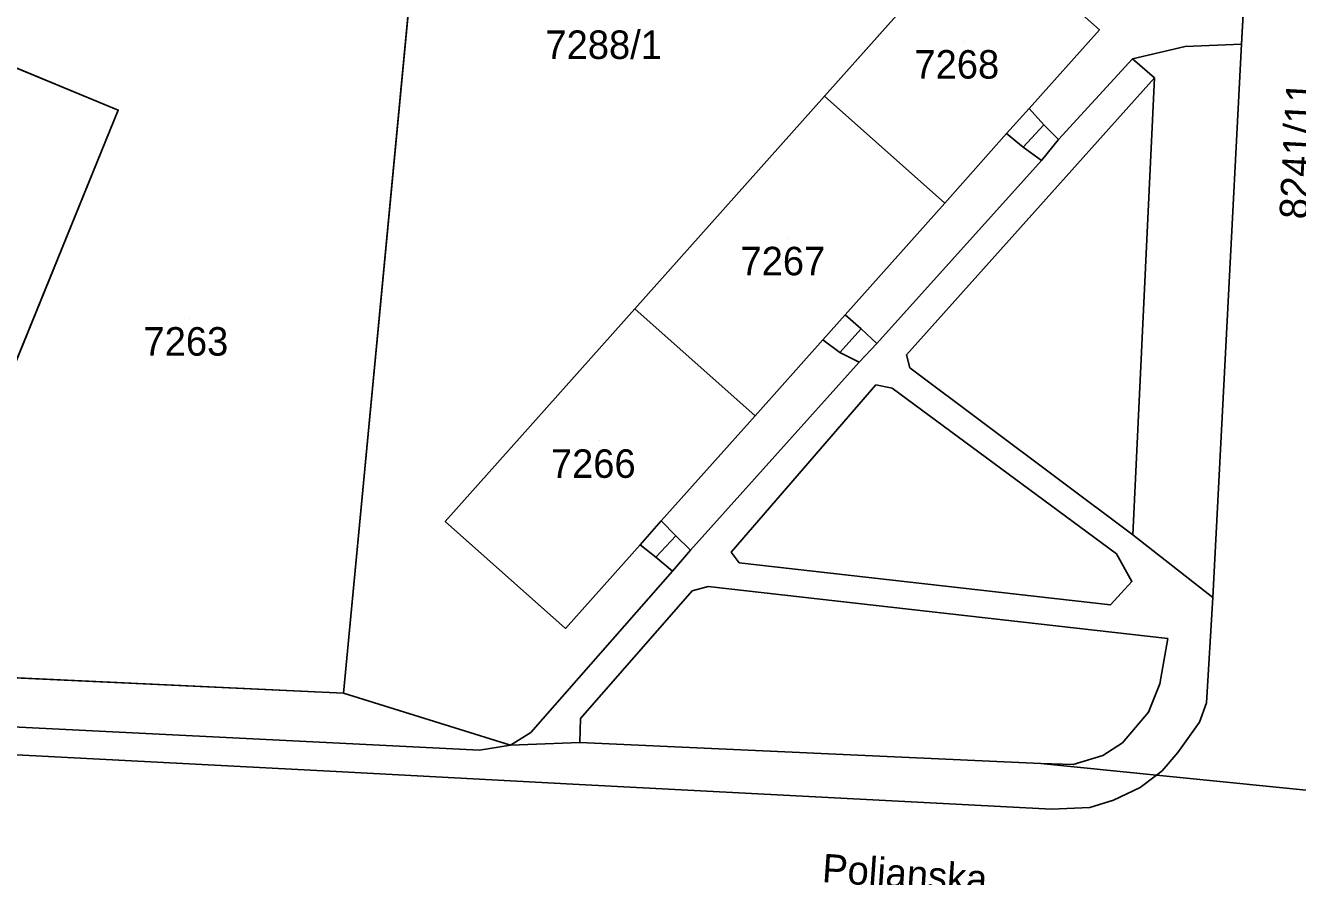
# Model space of a CAD drawing. Extents: x -266199 to -261993, y -1239047 to -1235108.
# Drawn here: x -263673.7 to -263584.5, y -1236465.2 to -1236405.4 of the extents above; entities that cross this region are included whole.
import ezdxf

# ---------------------------------------------------------------- set-up
doc = ezdxf.new("R2010")
doc.units = 0
for name, color, linetype in [('body_kn', 7, 'Continuous'), ('kladpar_druhypozemkov', 7, 'Continuous'), ('kladpar_hranice', 7, 'Continuous'), ('kladpar_parcelnecisla', 7, 'Continuous'), ('kladpar_plochy', 7, 'Continuous'), ('popisy', 7, 'Continuous'), ('zappar_hrandruhpozemk', 7, 'Continuous')]:
    doc.layers.add(name, color=color, linetype=linetype)

msp = doc.modelspace()

# ---------------------------------------------------------------- linework, layer by layer
at = {"layer": 'body_kn'}
for p, q in [((-263598.37, -1236405.73), (-263598.37, -1236405.73)), ((-263592.36, -1236406.91), (-263592.36, -1236406.91)), ((-263588.4, -1236406.75), (-263588.4, -1236406.75)), ((-263588.4, -1236406.75), (-263588.4, -1236406.75)), ((-263596.04, -1236407.78), (-263596.04, -1236407.78)), ((-263596.04, -1236407.78), (-263596.04, -1236407.78)), ((-263594.51, -1236409.11), (-263594.51, -1236409.11)), ((-263594.51, -1236409.11), (-263594.51, -1236409.11)), ((-263617.67, -1236410.39), (-263617.67, -1236410.39)), ((-263617.67, -1236410.39), (-263617.67, -1236410.39)), ((-263667.24, -1236411.37), (-263667.24, -1236411.37)), ((-263603.3, -1236411.26), (-263603.3, -1236411.26)), ((-263602.28, -1236412.4), (-263602.28, -1236412.4)), ((-263604.88, -1236413.02), (-263604.88, -1236413.02)), ((-263604.88, -1236413.02), (-263604.88, -1236413.02)), ((-263601.25, -1236413.44), (-263601.25, -1236413.44)), ((-263601.25, -1236413.44), (-263601.25, -1236413.44)), ((-263603.72, -1236413.98), (-263603.72, -1236413.98)), ((-263603.72, -1236413.98), (-263603.72, -1236413.98)), ((-263602.43, -1236414.91), (-263602.43, -1236414.91)), ((-263609.23, -1236417.91), (-263609.23, -1236417.91)), ((-263609.23, -1236417.91), (-263609.23, -1236417.91)), ((-263630.98, -1236425.33), (-263630.98, -1236425.33)), ((-263630.98, -1236425.33), (-263630.98, -1236425.33)), ((-263616.21, -1236425.74), (-263616.21, -1236425.74)), ((-263615.1, -1236426.73), (-263615.1, -1236426.73)), ((-263617.78, -1236427.5), (-263617.78, -1236427.5)), ((-263617.78, -1236427.5), (-263617.78, -1236427.5)), ((-263613.99, -1236427.76), (-263613.99, -1236427.76)), ((-263613.99, -1236427.76), (-263613.99, -1236427.76)), ((-263616.59, -1236428.4), (-263616.59, -1236428.4)), ((-263616.59, -1236428.4), (-263616.59, -1236428.4)), ((-263611.9, -1236428.55), (-263611.9, -1236428.55)), ((-263611.9, -1236428.55), (-263611.9, -1236428.55)), ((-263615.24, -1236429.07), (-263615.24, -1236429.07)), ((-263611.67, -1236429.47), (-263611.67, -1236429.47)), ((-263614.05, -1236430.67), (-263614.05, -1236430.67)), ((-263612.92, -1236430.89), (-263612.92, -1236430.89)), ((-263622.54, -1236432.83), (-263622.54, -1236432.83)), ((-263622.54, -1236432.83), (-263622.54, -1236432.83)), ((-263644.28, -1236440.26), (-263644.28, -1236440.26)), ((-263644.28, -1236440.26), (-263644.28, -1236440.26)), ((-263629.13, -1236440.22), (-263629.13, -1236440.22)), ((-263628.1, -1236441.27), (-263628.1, -1236441.27)), ((-263596.02, -1236441.19), (-263596.02, -1236441.19)), ((-263630.61, -1236441.89), (-263630.61, -1236441.89)), ((-263630.61, -1236441.89), (-263630.61, -1236441.89)), ((-263627.07, -1236442.26), (-263627.07, -1236442.26)), ((-263627.07, -1236442.26), (-263627.07, -1236442.26)), ((-263629.51, -1236442.76), (-263629.51, -1236442.76)), ((-263629.51, -1236442.76), (-263629.51, -1236442.76)), ((-263624.21, -1236442.4), (-263624.21, -1236442.4)), ((-263623.66, -1236443.15), (-263623.66, -1236443.15)), ((-263623.66, -1236443.15), (-263623.66, -1236443.15)), ((-263597.18, -1236442.53), (-263597.18, -1236442.53)), ((-263628.33, -1236443.75), (-263628.33, -1236443.75)), ((-263625.82, -1236444.81), (-263625.82, -1236444.81)), ((-263596.09, -1236444.47), (-263596.09, -1236444.47)), ((-263626.95, -1236445.13), (-263626.95, -1236445.13)), ((-263590.41, -1236445.58), (-263590.41, -1236445.58)), ((-263597.59, -1236446.11), (-263597.59, -1236446.11)), ((-263635.85, -1236447.76), (-263635.85, -1236447.76)), ((-263593.56, -1236448.48), (-263593.56, -1236448.48)), ((-263594.12, -1236451.65), (-263594.12, -1236451.65)), ((-263651.42, -1236452.3), (-263651.42, -1236452.3)), ((-263590.85, -1236452.98), (-263590.85, -1236452.98)), ((-263594.93, -1236453.64), (-263594.93, -1236453.64)), ((-263634.79, -1236454.08), (-263634.79, -1236454.08)), ((-263591.34, -1236454.35), (-263591.34, -1236454.35)), ((-263638.28, -1236455.08), (-263638.28, -1236455.08)), ((-263641.87, -1236456.31), (-263641.87, -1236456.31)), ((-263639.7, -1236455.97), (-263639.7, -1236455.97)), ((-263639.7, -1236455.97), (-263639.7, -1236455.97)), ((-263634.84, -1236455.76), (-263634.84, -1236455.76)), ((-263596.75, -1236455.79), (-263596.75, -1236455.79)), ((-263592.86, -1236456.48), (-263592.86, -1236456.48)), ((-263602.47, -1236457.24), (-263602.47, -1236457.24)), ((-263602.47, -1236457.24), (-263602.47, -1236457.24)), ((-263600.21, -1236457.31), (-263600.21, -1236457.31)), ((-263598.13, -1236456.69), (-263598.13, -1236456.69)), ((-263651.94, -1236457.81), (-263651.94, -1236457.81)), ((-263594.37, -1236458.06), (-263594.37, -1236458.06)), ((-263594.37, -1236458.06), (-263594.37, -1236458.06)), ((-263593.97, -1236457.75), (-263593.97, -1236457.75)), ((-263635.34, -1236458.69), (-263635.34, -1236458.69)), ((-263595.51, -1236458.93), (-263595.51, -1236458.93)), ((-263597.38, -1236459.82), (-263597.38, -1236459.82)), ((-263601.74, -1236460.46), (-263601.74, -1236460.46)), ((-263599.04, -1236460.33), (-263599.04, -1236460.33))]:
    msp.add_line(p, q, dxfattribs=at)
at = {"layer": 'kladpar_druhypozemkov'}
for p, q in [((-263607.89, -1236406.56), (-263607.89, -1236406.56)), ((-263620.17, -1236420.37), (-263620.17, -1236420.37)), ((-263662.21, -1236426.01), (-263662.21, -1236426.01)), ((-263633.43, -1236434.59), (-263633.43, -1236434.59))]:
    msp.add_line(p, q, dxfattribs=at)
at = {"layer": 'kladpar_hranice'}
for p, q in [((-263630.98, -1236425.33), (-263617.67, -1236410.39)), ((-263609.23, -1236417.91), (-263617.67, -1236410.39)), ((-263617.67, -1236410.39), (-263609.23, -1236417.91)), ((-263644.28, -1236440.26), (-263630.98, -1236425.33)), ((-263622.54, -1236432.83), (-263630.98, -1236425.33)), ((-263630.98, -1236425.33), (-263622.54, -1236432.83))]:
    msp.add_line(p, q, dxfattribs=at)
for points in [[(-263581.51, -1236459.36), (-263594.37, -1236458.06), (-263602.47, -1236457.24), (-263634.84, -1236455.76), (-263639.7, -1236455.97), (-263638.28, -1236455.08), (-263628.33, -1236443.75), (-263627.07, -1236442.26), (-263615.24, -1236429.07), (-263613.99, -1236427.76), (-263602.43, -1236414.91), (-263601.25, -1236413.44), (-263596.04, -1236407.78), (-263592.36, -1236406.91), (-263588.4, -1236406.75), (-263587.17, -1236384.74), (-263588.09, -1236383.59), (-263587.23, -1236367.19), (-263586.62, -1236353.93), (-263586.06, -1236340.81)], [(-263639.7, -1236455.97), (-263651.42, -1236452.3), (-263646.39, -1236399.38), (-263633.39, -1236364.05), (-263622.98, -1236368.95), (-263588.09, -1236383.59), (-263587.17, -1236384.74), (-263588.4, -1236406.75), (-263592.36, -1236406.91), (-263596.04, -1236407.78), (-263601.25, -1236413.44), (-263602.43, -1236414.91), (-263613.99, -1236427.76), (-263615.24, -1236429.07), (-263627.07, -1236442.26), (-263628.33, -1236443.75), (-263638.28, -1236455.08), (-263639.7, -1236455.97)], [(-263709.09, -1236449.61), (-263705.05, -1236441.25), (-263700.39, -1236432.21), (-263697.06, -1236424.67), (-263693.98, -1236417.08), (-263691.05, -1236409.36), (-263688.46, -1236401.51), (-263685.97, -1236393.68), (-263684.19, -1236387.52), (-263683.79, -1236386.13), (-263681.38, -1236386.98), (-263646.39, -1236399.38), (-263651.42, -1236452.3), (-263702.72, -1236449.91), (-263705.18, -1236449.79), (-263709.09, -1236449.61)], [(-263606.83, -1236398.22), (-263617.67, -1236410.39), (-263630.98, -1236425.33), (-263644.28, -1236440.26), (-263635.85, -1236447.76), (-263630.61, -1236441.89), (-263629.51, -1236442.76), (-263628.1, -1236441.27), (-263629.13, -1236440.22), (-263622.54, -1236432.83), (-263617.78, -1236427.5), (-263616.59, -1236428.4), (-263615.1, -1236426.73), (-263616.21, -1236425.74), (-263609.23, -1236417.91), (-263604.88, -1236413.02), (-263603.72, -1236413.98), (-263602.28, -1236412.4), (-263603.3, -1236411.26), (-263598.37, -1236405.73), (-263606.83, -1236398.22)], [(-263617.67, -1236410.39), (-263606.83, -1236398.22), (-263598.37, -1236405.73), (-263603.3, -1236411.26), (-263602.28, -1236412.4), (-263603.72, -1236413.98), (-263604.88, -1236413.02), (-263609.23, -1236417.91)], [(-263680.05, -1236442.84), (-263667.24, -1236411.37), (-263675.8, -1236407.84)], [(-263675.8, -1236407.84), (-263667.24, -1236411.37), (-263680.05, -1236442.84)], [(-263609.23, -1236417.91), (-263616.21, -1236425.74), (-263615.1, -1236426.73), (-263616.59, -1236428.4), (-263617.78, -1236427.5), (-263622.54, -1236432.83)], [(-263622.54, -1236432.83), (-263629.13, -1236440.22), (-263628.1, -1236441.27), (-263629.51, -1236442.76), (-263630.61, -1236441.89), (-263635.85, -1236447.76), (-263644.28, -1236440.26)], [(-263722.34, -1236467.48), (-263719.3, -1236463.54), (-263712.51, -1236454.77), (-263710.25, -1236451.5), (-263709.09, -1236449.61), (-263705.18, -1236449.79), (-263702.72, -1236449.91), (-263651.42, -1236452.3), (-263639.7, -1236455.97), (-263634.84, -1236455.76), (-263602.47, -1236457.24), (-263594.37, -1236458.06), (-263581.51, -1236459.36), (-263579.99, -1236460.55), (-263578.24, -1236461.24), (-263575.93, -1236461.68), (-263573.66, -1236461.77), (-263543.38, -1236463.29), (-263540.94, -1236463.26), (-263529.02, -1236464.2), (-263526.42, -1236463.65), (-263524.5, -1236462.92), (-263525.44, -1236474.41)]]:
    msp.add_lwpolyline(points, dxfattribs=at)
at = {"layer": 'kladpar_plochy'}
for p, q in [((-263587.17, -1236384.74), (-263588.4, -1236406.75)), ((-263606.83, -1236398.22), (-263617.67, -1236410.39)), ((-263598.37, -1236405.73), (-263606.83, -1236398.22)), ((-263651.42, -1236452.3), (-263646.39, -1236399.38)), ((-263646.39, -1236399.38), (-263651.42, -1236452.3)), ((-263603.3, -1236411.26), (-263598.37, -1236405.73)), ((-263592.36, -1236406.91), (-263596.04, -1236407.78)), ((-263588.4, -1236406.75), (-263592.36, -1236406.91)), ((-263667.24, -1236411.37), (-263675.8, -1236407.84)), ((-263596.04, -1236407.78), (-263601.25, -1236413.44)), ((-263617.67, -1236410.39), (-263630.98, -1236425.33)), ((-263680.05, -1236442.84), (-263667.24, -1236411.37)), ((-263602.28, -1236412.4), (-263603.3, -1236411.26)), ((-263603.72, -1236413.98), (-263602.28, -1236412.4)), ((-263609.23, -1236417.91), (-263604.88, -1236413.02)), ((-263604.88, -1236413.02), (-263603.72, -1236413.98)), ((-263601.25, -1236413.44), (-263602.43, -1236414.91)), ((-263602.43, -1236414.91), (-263613.99, -1236427.76)), ((-263616.21, -1236425.74), (-263609.23, -1236417.91)), ((-263630.98, -1236425.33), (-263644.28, -1236440.26)), ((-263615.1, -1236426.73), (-263616.21, -1236425.74)), ((-263616.59, -1236428.4), (-263615.1, -1236426.73)), ((-263622.54, -1236432.83), (-263617.78, -1236427.5)), ((-263617.78, -1236427.5), (-263616.59, -1236428.4)), ((-263613.99, -1236427.76), (-263615.24, -1236429.07)), ((-263615.24, -1236429.07), (-263627.07, -1236442.26)), ((-263629.13, -1236440.22), (-263622.54, -1236432.83)), ((-263644.28, -1236440.26), (-263635.85, -1236447.76)), ((-263628.1, -1236441.27), (-263629.13, -1236440.22)), ((-263629.51, -1236442.76), (-263628.1, -1236441.27)), ((-263635.85, -1236447.76), (-263630.61, -1236441.89)), ((-263630.61, -1236441.89), (-263629.51, -1236442.76)), ((-263627.07, -1236442.26), (-263628.33, -1236443.75)), ((-263628.33, -1236443.75), (-263638.28, -1236455.08)), ((-263651.42, -1236452.3), (-263702.72, -1236449.91)), ((-263639.7, -1236455.97), (-263651.42, -1236452.3)), ((-263638.28, -1236455.08), (-263639.7, -1236455.97))]:
    msp.add_line(p, q, dxfattribs=at)
for points in [[(-263581.51, -1236459.36), (-263594.37, -1236458.06), (-263602.47, -1236457.24), (-263634.84, -1236455.76), (-263639.7, -1236455.97), (-263638.28, -1236455.08), (-263628.33, -1236443.75), (-263627.07, -1236442.26), (-263615.24, -1236429.07), (-263613.99, -1236427.76), (-263602.43, -1236414.91), (-263601.25, -1236413.44), (-263596.04, -1236407.78), (-263592.36, -1236406.91), (-263588.4, -1236406.75), (-263587.17, -1236384.74), (-263588.09, -1236383.59), (-263587.23, -1236367.19), (-263586.62, -1236353.93), (-263586.06, -1236340.81)], [(-263675.8, -1236407.84), (-263667.24, -1236411.37), (-263680.05, -1236442.84)], [(-263722.34, -1236467.48), (-263719.3, -1236463.54), (-263712.51, -1236454.77), (-263710.25, -1236451.5), (-263709.09, -1236449.61), (-263705.18, -1236449.79), (-263702.72, -1236449.91), (-263651.42, -1236452.3), (-263639.7, -1236455.97), (-263634.84, -1236455.76), (-263602.47, -1236457.24), (-263594.37, -1236458.06), (-263581.51, -1236459.36), (-263579.99, -1236460.55), (-263578.24, -1236461.24), (-263575.93, -1236461.68), (-263573.66, -1236461.77), (-263543.38, -1236463.29), (-263540.94, -1236463.26), (-263529.02, -1236464.2), (-263526.42, -1236463.65), (-263524.5, -1236462.92), (-263525.44, -1236474.41)]]:
    msp.add_lwpolyline(points, dxfattribs=at)
for points in [[(-263617.67, -1236410.39), (-263606.83, -1236398.22), (-263598.37, -1236405.73), (-263603.3, -1236411.26), (-263602.28, -1236412.4), (-263603.72, -1236413.98), (-263604.88, -1236413.02), (-263609.23, -1236417.91)], [(-263630.98, -1236425.33), (-263617.67, -1236410.39), (-263609.23, -1236417.91), (-263616.21, -1236425.74), (-263615.1, -1236426.73), (-263616.59, -1236428.4), (-263617.78, -1236427.5), (-263622.54, -1236432.83)], [(-263644.28, -1236440.26), (-263630.98, -1236425.33), (-263622.54, -1236432.83), (-263629.13, -1236440.22), (-263628.1, -1236441.27), (-263629.51, -1236442.76), (-263630.61, -1236441.89), (-263635.85, -1236447.76)]]:
    msp.add_lwpolyline(points, close=True, dxfattribs=at)
at = {"layer": 'zappar_hrandruhpozemk'}
for p, q in [((-263588.4, -1236406.75), (-263590.41, -1236445.58)), ((-263596.04, -1236407.78), (-263594.51, -1236409.11)), ((-263611.9, -1236428.55), (-263594.51, -1236409.11)), ((-263604.88, -1236413.02), (-263603.3, -1236411.26)), ((-263601.25, -1236413.44), (-263602.28, -1236412.4)), ((-263603.72, -1236413.98), (-263602.43, -1236414.91)), ((-263617.78, -1236427.5), (-263616.21, -1236425.74)), ((-263613.99, -1236427.76), (-263615.1, -1236426.73)), ((-263616.59, -1236428.4), (-263615.24, -1236429.07)), ((-263611.67, -1236429.47), (-263611.9, -1236428.55)), ((-263612.92, -1236430.89), (-263597.18, -1236442.53)), ((-263630.61, -1236441.89), (-263629.13, -1236440.22)), ((-263627.07, -1236442.26), (-263628.1, -1236441.27)), ((-263629.51, -1236442.76), (-263628.33, -1236443.75)), ((-263593.56, -1236448.48), (-263625.82, -1236444.81)), ((-263601.74, -1236460.46), (-263635.34, -1236458.69))]:
    msp.add_line(p, q, dxfattribs=at)
for points in [[(-263594.51, -1236409.11), (-263596.02, -1236441.19), (-263611.67, -1236429.47)], [(-263623.66, -1236443.15), (-263624.21, -1236442.4), (-263614.05, -1236430.67), (-263612.92, -1236430.89)], [(-263594.37, -1236458.06), (-263593.97, -1236457.75), (-263592.86, -1236456.48), (-263591.34, -1236454.35), (-263590.85, -1236452.98), (-263590.41, -1236445.58), (-263596.02, -1236441.19)], [(-263597.18, -1236442.53), (-263596.09, -1236444.47), (-263597.59, -1236446.11), (-263623.66, -1236443.15)], [(-263625.82, -1236444.81), (-263626.95, -1236445.13), (-263634.79, -1236454.08), (-263634.84, -1236455.76)], [(-263602.47, -1236457.24), (-263600.21, -1236457.31), (-263598.13, -1236456.69), (-263596.75, -1236455.79), (-263594.93, -1236453.64), (-263594.12, -1236451.65), (-263593.56, -1236448.48)], [(-263639.7, -1236455.97), (-263641.87, -1236456.31), (-263681.7, -1236454.31)], [(-263635.34, -1236458.69), (-263651.94, -1236457.81), (-263682.02, -1236456.23)], [(-263594.37, -1236458.06), (-263595.51, -1236458.93), (-263597.38, -1236459.82), (-263599.04, -1236460.33), (-263601.74, -1236460.46)]]:
    msp.add_lwpolyline(points, dxfattribs=at)

# ---------------------------------------------------------------- texts
at = {"layer": 'kladpar_parcelnecisla'}
for s, p in [('7288/1', (-263637.253, -1236407.78)), ('7268', (-263611.353, -1236409.16)), ('7267', (-263623.562, -1236422.97)), ('7263', (-263665.462, -1236428.61)), ('7266', (-263636.869, -1236437.19))]:
    msp.add_text(s, height=2, dxfattribs=at).set_placement(p)
msp.add_text('8241/11', height=2, rotation=87, dxfattribs=at).set_placement((-263583.75, -1236419.067))
at = {"layer": 'popisy'}
msp.add_text('Polianska', height=2, rotation=356, dxfattribs=at).set_placement((-263617.877, -1236465.57))

doc.saveas('drawing.dxf')
